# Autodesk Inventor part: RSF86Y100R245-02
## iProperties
Created: 2007-10
Part Number: RSF86Y100R245-02
Material: 1.0037 St 37-2
Document SubType Name: Modellieren
Designer: TMT
Manufacturer: Standard
Standards Organization: Custom
Mass: 76.1822 g
Surface Area: 35.8121 cm^2
Volume: 9.70474 cm^3
Density: 7.85 g/cm^3
Author: TMT
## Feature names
1. Extrusion2
2. Extrusion3
3. Extrusion4
4. Extrusion5
5. Extrusion6
6. Rundung3 [Fillet]
